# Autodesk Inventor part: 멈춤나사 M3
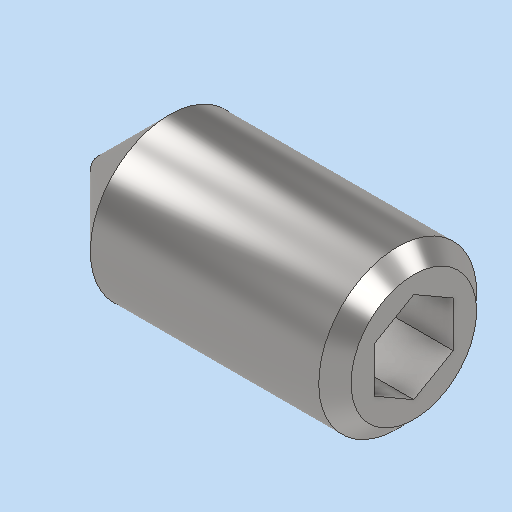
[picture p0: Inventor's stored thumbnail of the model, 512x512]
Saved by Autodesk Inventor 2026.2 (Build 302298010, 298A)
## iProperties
Created: 2026-08
Part Number: 멈춤나사 M3
Material: 강철, 연강
Description: 6각 소켓 머리 없는 멈춤 나사
Document SubType Name: Modeling
Designer: PC2-02
Density: 7.85 g/cm^3
Appearance: 기본값
Author: jhkim
Sending System: Autodesk Inventor 2027
Preprocessor: ST-DEVELOPER v20.1
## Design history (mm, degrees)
feature "Solid1"
node "솔리드1"
